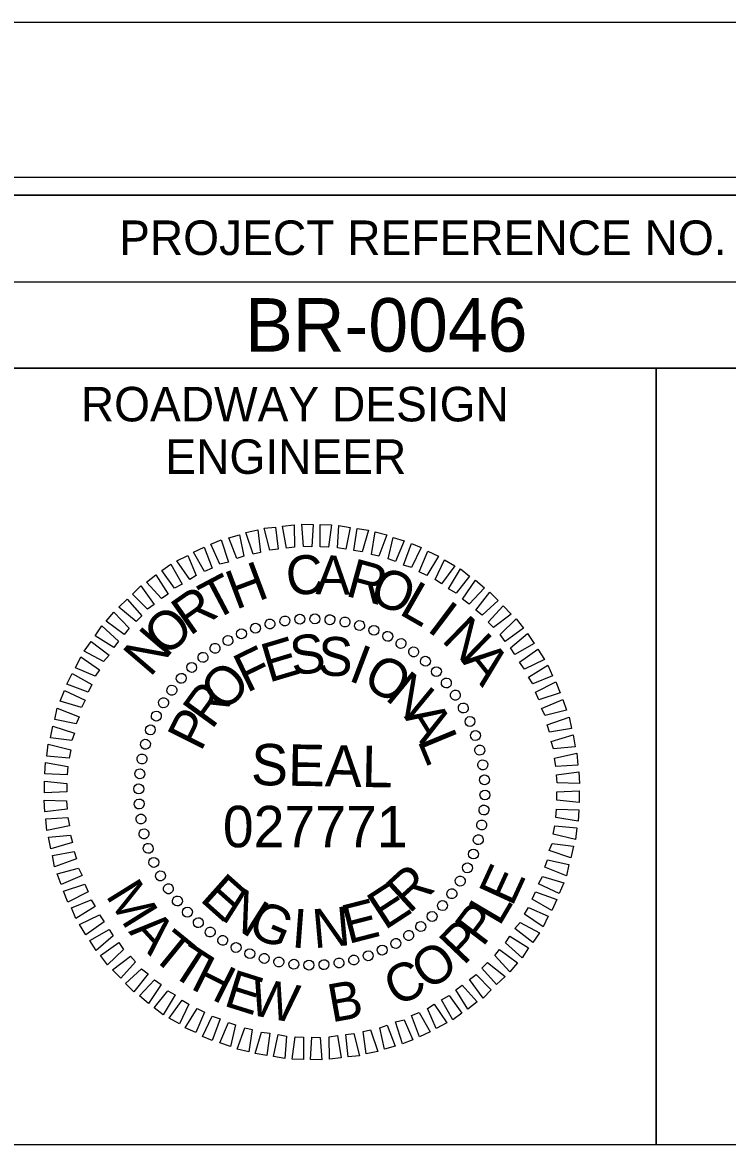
# Model space of a CAD drawing. Extents: x 1019474 to 1021161, y 504129 to 505324.
# Drawn here: x 1020949.4 to 1021051.6, y 505066.8 to 505229.3 of the extents above; entities that cross this region are included whole.
import ezdxf

# ---------------------------------------------------------------- set-up
doc = ezdxf.new("R2010")
doc.units = 0
for name, color, linetype in [('Sheet Cutting Line CELL', 7, 'Continuous'), ('Sheet Data Field CELL', 7, 'Continuous'), ('Sheet Plot Border Inside CELL', 7, 'Continuous'), ('Sheet Plot Border Outside CELL', 7, 'Continuous'), ('Sheet Professional Seal CELL', 7, 'Continuous'), ('Sheet Profile CELL', 7, 'Continuous'), ('Sheet Profile Grid Major CELL', 7, 'Continuous')]:
    doc.layers.add(name, color=color, linetype=linetype)

msp = doc.modelspace()

# ---------------------------------------------------------------- linework, layer by layer
at = {"layer": 'Sheet Cutting Line CELL'}
msp.add_line((1021158.22, 505229.29), (1019474.22, 505229.29), dxfattribs=at)
at = {"layer": 'Sheet Plot Border Inside CELL'}
msp.add_lwpolyline([(1019487.22, 504151.74), (1021153.72, 504151.74), (1021153.72, 505206.84), (1019487.22, 505206.84)], close=True, dxfattribs=at)
at = {"layer": 'Sheet Plot Border Outside CELL'}
msp.add_lwpolyline([(1019474.22, 504129.29), (1021158.22, 504129.29), (1021158.22, 505229.29), (1019474.22, 505229.29)], close=True, dxfattribs=at)
at = {"layer": 'Sheet Professional Seal CELL'}
for p, q in [((1020987.42, 505142.59), (1020987.42, 505142.59)), ((1020989.57, 505142.89), (1020989.57, 505142.89)), ((1020991.77, 505142.94), (1020991.77, 505142.94)), ((1020993.97, 505142.79), (1020993.97, 505142.79)), ((1020996.12, 505142.44), (1020996.12, 505142.44)), ((1020981.12, 505140.79), (1020981.12, 505140.79)), ((1020983.12, 505141.59), (1020983.12, 505141.59)), ((1020985.22, 505142.19), (1020985.22, 505142.19)), ((1020998.22, 505141.99), (1020998.22, 505141.99)), ((1021000.32, 505141.29), (1021000.32, 505141.29)), ((1020979.17, 505139.79), (1020979.17, 505139.79)), ((1021002.32, 505140.39), (1021002.32, 505140.39)), ((1021004.27, 505139.39), (1021004.27, 505139.39)), ((1020977.27, 505138.64), (1020977.27, 505138.64)), ((1021006.07, 505138.14), (1021006.07, 505138.14)), ((1020973.87, 505135.89), (1020973.87, 505135.89)), ((1020975.52, 505137.39), (1020975.52, 505137.39)), ((1021007.82, 505136.79), (1021007.82, 505136.79)), ((1020972.37, 505134.34), (1020972.37, 505134.34)), ((1021009.37, 505135.29), (1021009.37, 505135.29)), ((1020971.02, 505132.59), (1020971.02, 505132.59)), ((1021010.87, 505133.64), (1021010.87, 505133.64)), ((1021012.12, 505131.89), (1021012.12, 505131.89)), ((1020969.77, 505130.79), (1020969.77, 505130.79)), ((1021013.27, 505129.99), (1021013.27, 505129.99)), ((1020968.77, 505128.84), (1020968.77, 505128.84)), ((1021014.27, 505128.04), (1021014.27, 505128.04)), ((1020967.87, 505126.84), (1020967.87, 505126.84)), ((1020967.17, 505124.74), (1020967.17, 505124.74)), ((1021015.07, 505126.04), (1021015.07, 505126.04)), ((1021015.67, 505123.94), (1021015.67, 505123.94)), ((1020966.72, 505122.64), (1020966.72, 505122.64)), ((1021016.07, 505121.74), (1021016.07, 505121.74)), ((1020966.37, 505120.49), (1020966.37, 505120.49)), ((1021016.37, 505119.59), (1021016.37, 505119.59)), ((1020966.22, 505118.29), (1020966.22, 505118.29)), ((1020991.32, 505117.84), (1020991.32, 505117.84)), ((1021016.42, 505117.39), (1021016.42, 505117.39)), ((1020966.27, 505116.09), (1020966.27, 505116.09)), ((1021016.27, 505115.19), (1021016.27, 505115.19)), ((1020966.57, 505113.94), (1020966.57, 505113.94)), ((1020966.97, 505111.74), (1020966.97, 505111.74)), ((1021015.92, 505113.04), (1021015.92, 505113.04)), ((1021015.47, 505110.94), (1021015.47, 505110.94)), ((1020967.57, 505109.64), (1020967.57, 505109.64)), ((1021014.77, 505108.84), (1021014.77, 505108.84)), ((1020968.37, 505107.64), (1020968.37, 505107.64)), ((1021013.87, 505106.84), (1021013.87, 505106.84)), ((1020969.37, 505105.69), (1020969.37, 505105.69)), ((1020970.52, 505103.79), (1020970.52, 505103.79)), ((1021012.87, 505104.89), (1021012.87, 505104.89)), ((1020971.77, 505102.04), (1020971.77, 505102.04)), ((1021011.62, 505103.09), (1021011.62, 505103.09)), ((1020973.27, 505100.39), (1020973.27, 505100.39)), ((1021010.27, 505101.34), (1021010.27, 505101.34)), ((1020974.82, 505098.89), (1020974.82, 505098.89)), ((1021008.77, 505099.79), (1021008.77, 505099.79)), ((1020976.57, 505097.54), (1020976.57, 505097.54)), ((1021005.37, 505097.04), (1021005.37, 505097.04)), ((1021007.12, 505098.29), (1021007.12, 505098.29)), ((1020978.37, 505096.29), (1020978.37, 505096.29)), ((1020980.32, 505095.29), (1020980.32, 505095.29)), ((1021003.47, 505095.89), (1021003.47, 505095.89)), ((1020982.32, 505094.39), (1020982.32, 505094.39)), ((1020984.42, 505093.69), (1020984.42, 505093.69)), ((1020999.52, 505094.09), (1020999.52, 505094.09)), ((1021001.52, 505094.89), (1021001.52, 505094.89)), ((1020986.52, 505093.24), (1020986.52, 505093.24)), ((1020988.67, 505092.89), (1020988.67, 505092.89)), ((1020990.87, 505092.74), (1020990.87, 505092.74)), ((1020993.07, 505092.79), (1020993.07, 505092.79)), ((1020995.22, 505093.09), (1020995.22, 505093.09)), ((1020997.42, 505093.49), (1020997.42, 505093.49))]:
    msp.add_line(p, q, dxfattribs=at)
for points in [[(1020982.82, 505152.29), (1020981.77, 505155.44), (1020983.47, 505155.79), (1020983.87, 505152.54)], [(1020985.22, 505152.84), (1020984.42, 505156.04), (1020986.07, 505156.19), (1020986.42, 505152.99)], [(1020987.62, 505153.14), (1020987.07, 505156.34), (1020988.77, 505156.54), (1020988.82, 505153.29)], [(1020990.12, 505153.39), (1020989.87, 505156.64), (1020991.52, 505156.59), (1020991.32, 505153.34)], [(1020992.52, 505153.34), (1020992.52, 505156.59), (1020994.17, 505156.54), (1020993.72, 505153.29)], [(1020995.02, 505153.19), (1020995.22, 505156.44), (1020996.87, 505156.14), (1020996.22, 505152.99)], [(1020997.42, 505152.79), (1020997.87, 505155.99), (1020999.52, 505155.74), (1020998.62, 505152.64)], [(1020999.97, 505152.24), (1021000.47, 505155.49), (1021002.17, 505155.09), (1021001.02, 505151.99)], [(1020977.97, 505150.84), (1020976.67, 505153.74), (1020978.17, 505154.34), (1020979.22, 505151.14)], [(1020980.42, 505151.64), (1020979.27, 505154.64), (1020980.82, 505155.09), (1020981.47, 505151.99)], [(1021002.37, 505151.59), (1021003.12, 505154.69), (1021004.67, 505154.19), (1021003.42, 505151.24)], [(1021004.62, 505150.69), (1021005.77, 505153.84), (1021007.17, 505153.24), (1021005.77, 505150.34)], [(1020973.62, 505148.59), (1020971.77, 505151.29), (1020973.32, 505152.09), (1020974.57, 505149.19)], [(1020975.77, 505149.79), (1020974.17, 505152.59), (1020975.72, 505153.29), (1020976.87, 505150.24)], [(1021006.87, 505149.74), (1021008.12, 505152.69), (1021009.67, 505151.99), (1021007.97, 505149.19)], [(1020971.42, 505147.34), (1020969.57, 505149.89), (1020970.87, 505150.84), (1020972.52, 505147.94)], [(1021009.17, 505148.59), (1021010.52, 505151.44), (1021012.02, 505150.59), (1021010.12, 505147.99)], [(1020969.52, 505145.84), (1020967.37, 505148.24), (1020968.72, 505149.29), (1020970.47, 505146.49)], [(1021011.12, 505147.24), (1021012.87, 505150.14), (1021014.17, 505149.09), (1021012.22, 505146.64)], [(1020967.52, 505144.29), (1020965.32, 505146.49), (1020966.52, 505147.69), (1020968.47, 505144.99)], [(1021013.17, 505145.74), (1021015.02, 505148.49), (1021016.32, 505147.39), (1021014.12, 505145.04)], [(1020965.87, 505142.54), (1020963.32, 505144.59), (1020964.57, 505145.74), (1020966.67, 505143.34)], [(1021015.07, 505144.19), (1021017.12, 505146.79), (1021018.32, 505145.59), (1021016.02, 505143.44)], [(1021016.87, 505142.44), (1021019.02, 505144.79), (1021020.22, 505143.59), (1021017.62, 505141.64)], [(1020964.12, 505140.64), (1020961.52, 505142.59), (1020962.62, 505143.89), (1020964.82, 505141.54)], [(1021018.62, 505140.64), (1021020.92, 505142.89), (1021021.97, 505141.54), (1021019.32, 505139.64)], [(1020962.62, 505138.74), (1020959.92, 505140.44), (1020960.87, 505141.89), (1020963.27, 505139.69)], [(1021020.12, 505138.69), (1021022.57, 505140.79), (1021023.52, 505139.34), (1021020.72, 505137.74)], [(1020961.12, 505136.74), (1020958.32, 505138.24), (1020959.32, 505139.64), (1020961.92, 505137.64)], [(1021021.42, 505136.64), (1021024.07, 505138.54), (1021025.02, 505137.04), (1021022.12, 505135.64)], [(1020959.92, 505134.59), (1020957.07, 505135.84), (1020957.82, 505137.39), (1020960.52, 505135.54)], [(1021022.72, 505134.44), (1021025.52, 505136.19), (1021026.17, 505134.64), (1021023.32, 505133.49)], [(1020958.92, 505132.29), (1020955.82, 505133.44), (1020956.57, 505134.99), (1020959.42, 505133.39)], [(1021023.72, 505132.29), (1021026.67, 505133.79), (1021027.32, 505132.19), (1021024.22, 505131.19)], [(1020957.92, 505130.09), (1020954.82, 505130.99), (1020955.47, 505132.54), (1020958.47, 505131.14)], [(1021024.62, 505129.94), (1021027.67, 505131.24), (1021028.22, 505129.69), (1021025.12, 505128.89)], [(1020957.17, 505127.69), (1020954.07, 505128.34), (1020954.42, 505129.99), (1020957.57, 505128.74)], [(1021025.42, 505127.54), (1021028.62, 505128.69), (1021028.92, 505127.04), (1021025.77, 505126.49)], [(1020956.52, 505125.29), (1020953.42, 505125.69), (1020953.77, 505127.39), (1020956.92, 505126.34)], [(1021026.02, 505125.14), (1021029.17, 505126.09), (1021029.47, 505124.39), (1021026.32, 505124.09)], [(1020956.12, 505122.74), (1020952.92, 505123.04), (1020953.12, 505124.74), (1020956.37, 505123.94)], [(1021026.47, 505122.74), (1021029.72, 505123.44), (1021029.87, 505121.74), (1021026.67, 505121.54)], [(1020955.87, 505120.34), (1020952.62, 505120.44), (1020952.72, 505122.09), (1020955.97, 505121.54)], [(1021026.77, 505120.34), (1021030.02, 505120.74), (1021030.12, 505119.04), (1021026.87, 505119.14)], [(1020955.82, 505117.84), (1020952.57, 505117.69), (1020952.57, 505119.39), (1020955.82, 505119.04)], [(1021026.82, 505117.84), (1021030.07, 505117.99), (1021030.07, 505116.29), (1021026.82, 505116.64)], [(1020955.87, 505115.34), (1020952.62, 505114.94), (1020952.52, 505116.64), (1020955.77, 505116.54)], [(1021026.77, 505115.34), (1021030.02, 505115.24), (1021029.92, 505113.59), (1021026.67, 505114.14)], [(1020956.17, 505112.94), (1020952.92, 505112.24), (1020952.77, 505113.94), (1020955.97, 505114.14)], [(1020956.62, 505110.54), (1020953.47, 505109.59), (1020953.17, 505111.29), (1020956.32, 505111.59)], [(1021026.52, 505112.94), (1021029.72, 505112.64), (1021029.52, 505110.94), (1021026.27, 505111.74)], [(1021026.12, 505110.39), (1021029.22, 505109.99), (1021028.87, 505108.29), (1021025.72, 505109.34)], [(1020957.22, 505108.14), (1020954.02, 505106.99), (1020953.72, 505108.64), (1020956.87, 505109.19)], [(1020958.02, 505105.74), (1020954.97, 505104.44), (1020954.42, 505105.99), (1020957.52, 505106.79)], [(1021025.47, 505107.99), (1021028.57, 505107.34), (1021028.22, 505105.69), (1021025.07, 505106.94)], [(1021024.72, 505105.59), (1021027.82, 505104.69), (1021027.17, 505103.14), (1021024.17, 505104.54)], [(1020958.92, 505103.39), (1020955.97, 505101.89), (1020955.32, 505103.49), (1020958.42, 505104.49)], [(1021023.72, 505103.39), (1021026.82, 505102.24), (1021026.07, 505100.69), (1021023.22, 505102.29)], [(1020959.92, 505101.24), (1020957.12, 505099.49), (1020956.47, 505101.04), (1020959.32, 505102.19)], [(1021022.72, 505101.09), (1021025.57, 505099.84), (1021024.82, 505098.29), (1021022.12, 505100.14)], [(1020961.22, 505099.04), (1020958.57, 505097.14), (1020957.62, 505098.64), (1020960.52, 505100.04)], [(1021021.52, 505098.94), (1021024.32, 505097.44), (1021023.32, 505096.04), (1021020.72, 505098.04)], [(1020962.52, 505096.99), (1020960.07, 505094.89), (1020959.12, 505096.34), (1020961.92, 505097.94)], [(1021020.02, 505096.94), (1021022.72, 505095.24), (1021021.77, 505093.79), (1021019.37, 505095.99)], [(1020964.02, 505095.04), (1020961.72, 505092.79), (1020960.67, 505094.14), (1020963.32, 505096.04)], [(1020965.77, 505093.24), (1020963.62, 505090.89), (1020962.42, 505092.09), (1020965.02, 505094.04)], [(1021018.52, 505095.04), (1021021.12, 505093.09), (1021020.02, 505091.79), (1021017.82, 505094.14)], [(1020967.57, 505091.49), (1020965.52, 505088.89), (1020964.32, 505090.09), (1020966.62, 505092.24)], [(1021016.77, 505093.14), (1021019.32, 505091.09), (1021018.07, 505089.94), (1021015.97, 505092.34)], [(1020969.47, 505089.94), (1020967.62, 505087.19), (1020966.32, 505088.29), (1020968.52, 505090.64)], [(1021015.12, 505091.39), (1021017.32, 505089.19), (1021016.12, 505087.99), (1021014.17, 505090.69)], [(1020971.52, 505088.44), (1020969.77, 505085.54), (1020968.47, 505086.59), (1020970.42, 505089.04)], [(1021013.12, 505089.84), (1021015.27, 505087.44), (1021013.92, 505086.39), (1021012.17, 505089.19)], [(1020973.47, 505087.09), (1020972.12, 505084.24), (1020970.62, 505085.09), (1020972.52, 505087.69)], [(1021009.02, 505087.09), (1021010.87, 505084.39), (1021009.32, 505083.59), (1021008.07, 505086.49)], [(1021011.22, 505088.34), (1021013.07, 505085.79), (1021011.77, 505084.84), (1021010.12, 505087.74)], [(1020975.77, 505085.94), (1020974.52, 505082.99), (1020972.97, 505083.69), (1020974.67, 505086.49)], [(1021006.87, 505085.89), (1021008.47, 505083.09), (1021006.92, 505082.39), (1021005.77, 505085.44)], [(1020978.02, 505084.99), (1020976.87, 505081.84), (1020975.47, 505082.44), (1020976.87, 505085.34)], [(1020980.27, 505084.09), (1020979.52, 505080.99), (1020977.97, 505081.49), (1020979.22, 505084.44)], [(1021002.22, 505084.04), (1021003.37, 505081.04), (1021001.82, 505080.59), (1021001.17, 505083.69)], [(1021004.67, 505084.84), (1021005.97, 505081.94), (1021004.47, 505081.34), (1021003.42, 505084.54)], [(1020982.67, 505083.44), (1020982.17, 505080.19), (1020980.47, 505080.59), (1020981.62, 505083.69)], [(1020985.22, 505082.89), (1020984.77, 505079.69), (1020983.12, 505079.94), (1020984.02, 505083.04)], [(1020987.62, 505082.49), (1020987.42, 505079.24), (1020985.77, 505079.54), (1020986.42, 505082.69)], [(1020990.12, 505082.34), (1020990.12, 505079.09), (1020988.47, 505079.14), (1020988.92, 505082.39)], [(1020992.52, 505082.29), (1020992.77, 505079.04), (1020991.12, 505079.09), (1020991.32, 505082.34)], [(1020995.02, 505082.54), (1020995.57, 505079.34), (1020993.87, 505079.14), (1020993.82, 505082.39)], [(1020997.42, 505082.84), (1020998.22, 505079.64), (1020996.57, 505079.49), (1020996.22, 505082.69)], [(1020999.82, 505083.39), (1021000.87, 505080.24), (1020999.17, 505079.89), (1020998.77, 505083.14)]]:
    msp.add_lwpolyline(points, close=True, dxfattribs=at)
for centre, major_axis in [((1020983.15, 505141.55), (-0.234, 0.681)), ((1020985.25, 505142.17), (-0.174, 0.699)), ((1020987.4, 505142.61), (-0.113, 0.711)), ((1020989.57, 505142.86), (-0.05, 0.718)), ((1020991.76, 505142.91), (0.013, 0.72)), ((1020993.94, 505142.78), (0.075, 0.716)), ((1020996.11, 505142.46), (0.137, 0.707)), ((1020998.23, 505141.95), (0.198, 0.692)), ((1020981.12, 505140.75), (-0.293, 0.658)), ((1021000.31, 505141.25), (0.258, 0.672)), ((1021002.31, 505140.38), (0.316, 0.647)), ((1020977.29, 505138.63), (-0.403, 0.597)), ((1020979.16, 505139.77), (-0.349, 0.63)), ((1021004.24, 505139.34), (0.371, 0.617)), ((1020975.54, 505137.33), (-0.453, 0.56)), ((1021006.06, 505138.13), (0.423, 0.582)), ((1021007.77, 505136.77), (0.472, 0.543)), ((1020973.9, 505135.88), (-0.5, 0.518)), ((1021009.36, 505135.26), (0.518, 0.5)), ((1020972.39, 505134.29), (-0.543, 0.472)), ((1021010.81, 505133.62), (0.56, 0.453)), ((1020971.03, 505132.58), (-0.582, 0.423)), ((1021012.11, 505131.86), (0.597, 0.403)), ((1020969.82, 505130.75), (-0.617, 0.371)), ((1020968.78, 505128.83), (-0.647, 0.316)), ((1021013.26, 505130), (0.63, 0.349)), ((1021014.23, 505128.04), (0.658, 0.293)), ((1020967.91, 505126.83), (-0.672, 0.258)), ((1021015.03, 505126), (0.681, 0.234)), ((1020967.21, 505124.75), (-0.692, 0.198)), ((1021015.65, 505123.9), (0.699, 0.174)), ((1020966.7, 505122.62), (-0.707, 0.137)), ((1020966.38, 505120.46), (-0.716, 0.075)), ((1021016.09, 505121.76), (0.711, 0.113)), ((1021016.34, 505119.59), (0.718, 0.05)), ((1020966.24, 505118.28), (-0.72, 0.013)), ((1021016.4, 505117.4), (0.72, -0.013)), ((1020966.3, 505116.09), (-0.718, -0.05)), ((1021016.26, 505115.22), (0.716, -0.075)), ((1020966.55, 505113.91), (-0.711, -0.113)), ((1021015.94, 505113.05), (0.707, -0.137)), ((1020966.98, 505111.77), (-0.699, -0.174)), ((1021015.43, 505110.92), (0.692, -0.198)), ((1020967.61, 505109.67), (-0.681, -0.234)), ((1020968.41, 505107.64), (-0.658, -0.293)), ((1021014.73, 505108.85), (0.672, -0.258)), ((1021013.86, 505106.84), (0.647, -0.316)), ((1020969.38, 505105.68), (-0.63, -0.349)), ((1021012.82, 505104.92), (0.617, -0.371)), ((1020970.53, 505103.81), (-0.597, -0.403)), ((1021011.61, 505103.1), (0.582, -0.423)), ((1020971.83, 505102.05), (-0.56, -0.453)), ((1021010.25, 505101.38), (0.543, -0.472)), ((1020973.28, 505100.42), (-0.518, -0.5)), ((1021008.74, 505099.8), (0.5, -0.518)), ((1020974.87, 505098.91), (-0.472, -0.543)), ((1021007.1, 505098.35), (0.453, -0.56)), ((1020976.58, 505097.55), (-0.423, -0.582)), ((1020978.4, 505096.34), (-0.371, -0.617)), ((1021005.34, 505097.05), (0.403, -0.597)), ((1020980.33, 505095.3), (-0.316, -0.647)), ((1020982.33, 505094.42), (-0.258, -0.672)), ((1021001.52, 505094.93), (0.293, -0.658)), ((1021003.48, 505095.9), (0.349, -0.63)), ((1020984.41, 505093.73), (-0.198, -0.692)), ((1020986.53, 505093.22), (-0.137, -0.707)), ((1020988.7, 505092.89), (-0.075, -0.716)), ((1020995.24, 505093.07), (0.113, -0.711)), ((1020997.39, 505093.5), (0.174, -0.699)), ((1020999.48, 505094.12), (0.234, -0.681)), ((1020990.88, 505092.76), (-0.013, -0.72)), ((1020993.07, 505092.82), (0.05, -0.718))]:
    msp.add_ellipse(centre, major_axis=major_axis, ratio=0.999708, dxfattribs=at)
at = {"layer": 'Sheet Profile CELL'}
for p, q in [((1020941.17, 505191.74), (1021141.22, 505191.74)), ((1021041.22, 505179.24), (1021041.22, 505066.79))]:
    msp.add_line(p, q, dxfattribs=at)
for points in [[(1021141.22, 505204.29), (1019641.22, 505204.29), (1019641.22, 504154.29), (1021141.22, 504154.29)], [(1020941.17, 505204.29), (1021141.22, 505204.29), (1021141.22, 505179.24), (1020941.17, 505179.24)], [(1020941.17, 505179.24), (1021041.22, 505179.24), (1021041.22, 505066.74), (1020941.17, 505066.74)], [(1021041.22, 505179.24), (1021141.22, 505179.24), (1021141.22, 505066.74), (1021041.22, 505066.74)]]:
    msp.add_lwpolyline(points, close=True, dxfattribs=at)
at = {"layer": 'Sheet Profile Grid Major CELL'}
msp.add_lwpolyline([(1020641.22, 505204.29), (1020691.22, 505204.29), (1020691.22, 504704.29), (1020741.22, 504704.29), (1020741.22, 505204.29), (1020791.22, 505204.29), (1020791.22, 504704.29), (1020841.22, 504704.29), (1020841.22, 505204.29), (1020891.22, 505204.29), (1020891.22, 504704.29), (1020941.22, 504704.29), (1020941.22, 505204.29), (1020967.52, 505204.29)], dxfattribs=at)

# ---------------------------------------------------------------- texts
at = {"layer": 'Sheet Data Field CELL'}
msp.add_text('BR-0046', height=7.75, dxfattribs=at).set_placement((1020981.65, 505181.61))
at = {"layer": 'Sheet Professional Seal CELL'}
for s, height, rotation, p in [('C', 5.64, 6.2199, (1020987.87, 505146.19)), ('A', 5.64, 359.0203, (1020991.82, 505146.49)), ('H', 5.64, 20.6195, (1020980.27, 505144.19)), ('R', 5.64, 344.6211, (1020996.02, 505146.29)), ('T', 5.64, 27.8198, (1020977.02, 505142.54)), ('O', 5.64, 337.4212, (1020999.37, 505145.54)), ('R', 5.64, 35.0205, (1020973.62, 505140.34)), ('L', 5.64, 330.2209, (1021003.77, 505143.69)), ('O', 5.64, 42.2217, (1020970.17, 505137.24)), ('I', 5.64, 323.0201, (1021007.82, 505141.29)), ('N', 5.64, 315.8189, (1021009.97, 505139.74)), ('N', 5.64, 49.4235, (1020967.87, 505134.34)), ('S', 5.64, 7.2556, (1020988.52, 505134.69)), ('F', 5.64, 25.967, (1020981.87, 505132.14)), ('E', 5.64, 16.6111, (1020985.07, 505133.64)), ('S', 5.64, 357.9004, (1020992.12, 505134.74)), ('I', 5.64, 339.1896, (1020996.42, 505134.04)), ('A', 5.64, 308.6172, (1021012.92, 505136.79)), ('O', 5.64, 44.6812, (1020978.57, 505129.19)), ('O', 5.64, 329.8335, (1020998.42, 505133.34)), ('N', 5.64, 320.4766, (1021001.77, 505131.34)), ('R', 5.64, 54.0397, (1020976.82, 505126.74)), ('P', 5.64, 63.3989, (1020975.22, 505123.54)), ('A', 5.64, 301.7603, (1021004.62, 505128.74)), ('L', 5.64, 292.4008, (1021006.57, 505125.29)), ('SEAL', 5.998, 359, (1020982.47, 505118.84)), ('027771', 5.998, 360, (1020978.42, 505109.83)), ('R', 5.64, 42.4814, (1021005.42, 505100.09)), ('E', 5.5, 65.3458, (1021020.35, 505101.1)), ('M', 5.5, 301.8863, (1020961.35, 505102.85)), ('E', 5.64, 318.2769, (1020974.92, 505102.19)), ('E', 5.64, 33.1241, (1021001.87, 505097.74)), ('N', 5.64, 327.634, (1020977.92, 505099.49)), ('G', 5.64, 336.9902, (1020981.72, 505097.24)), ('E', 5.64, 14.4118, (1020996.57, 505095.79)), ('L', 5.5, 59.5356, (1021018.5, 505098.24)), ('I', 5.64, 355.7012, (1020988.27, 505095.34)), ('N', 5.64, 5.0564, (1020991.62, 505095.19)), ('P', 5.5, 52.9527, (1021016.08, 505095.26)), ('A', 5.5, 312.5622, (1020964.64, 505097.56)), ('P', 5.5, 46.3697, (1021013.32, 505092.57)), ('T', 5.5, 320.748, (1020967.8, 505093.97)), ('T', 5.5, 327.0447, (1020970.56, 505091.53)), ('O', 5.5, 35.6652, (1021008.25, 505088.92)), ('H', 5.5, 333.3415, (1020973.57, 505089.41)), ('E', 5.5, 342.5863, (1020978.37, 505086.93)), ('C', 5.5, 26.7925, (1021003.58, 505086.65)), ('W', 5.5, 349.1693, (1020982, 505085.65)), ('B', 5.5, 10.2205, (1020994.18, 505084.45))]:
    msp.add_text(s, height=height, rotation=rotation, dxfattribs=at).set_placement(p)
at = {"layer": 'Sheet Profile CELL'}
for s, height, p in [('PROJECT REFERENCE NO.', 5.0001, (1020963.38, 505195.61)), ('ROADWAY DESIGN', 5.0001, (1020957.83, 505171.51)), ('ENGINEER', 5, (1020970.08, 505163.91))]:
    msp.add_text(s, height=height, dxfattribs=at).set_placement(p)

doc.saveas('drawing.dxf')
